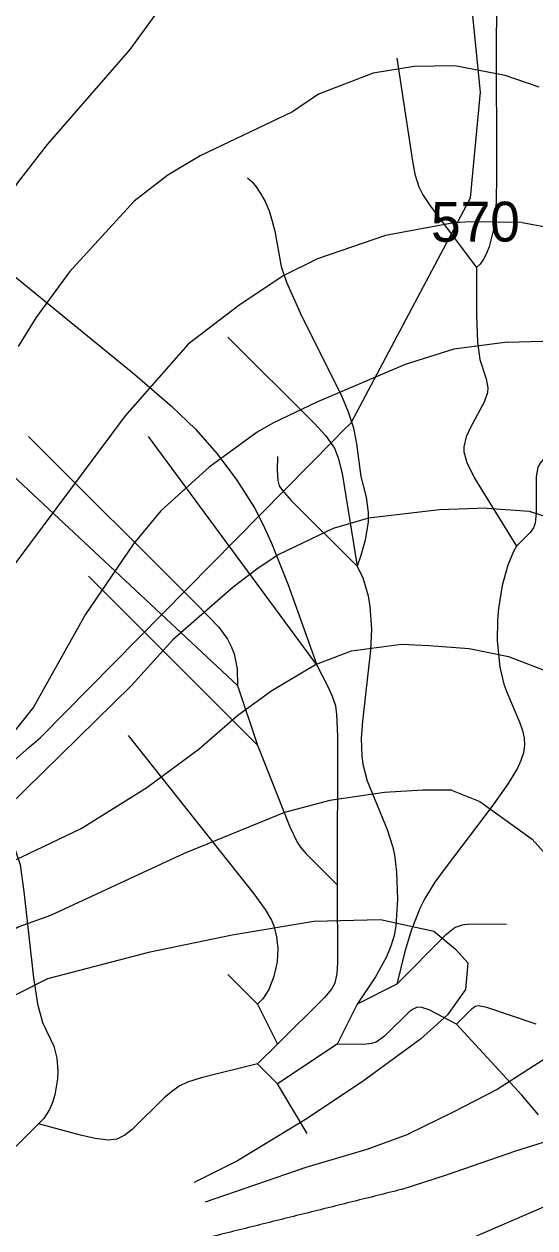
# Model space of a CAD drawing. Extents: x -709584 to -702006, y -1161789 to -1157496.
# Drawn here: x -706590.6 to -706462.3, y -1158463.2 to -1158160.9 of the extents above; entities that cross this region are included whole.
import ezdxf

# ---------------------------------------------------------------- set-up
doc = ezdxf.new("R2010")
doc.units = 0
for name, color, linetype in [('120_vrstevnice hlavní', 7, 'Continuous'), ('121_vrstevnice hlavní_popis', 7, 'Continuous'), ('122_vrstevnice základní', 7, 'Continuous'), ('408_BPEJ_linie', 7, 'Continuous'), ('411_akumulovaný odtok', 7, 'Continuous')]:
    doc.layers.add(name, color=color, linetype=linetype)

msp = doc.modelspace()

# ---------------------------------------------------------------- linework, layer by layer
at = {"layer": '120_vrstevnice hlavní'}
for points in [[(-706465.49, -1158210.75), (-706478.4, -1158210.55), (-706482.68, -1158210.83), (-706499.82, -1158213.98), (-706516.97, -1158219.83), (-706525.54, -1158224.12), (-706536.68, -1158231.55), (-706549.4, -1158241.26), (-706565.26, -1158259.27), (-706592.97, -1158296.41), (-706602.69, -1158311.7), (-706614.66, -1158334.43)], [(-706465.49, -1158210.75), (-706457.4, -1158212.2), (-706445.84, -1158215.99), (-706434.55, -1158221.69), (-706425.49, -1158219.2), (-706412.53, -1158232.56)], [(-706653.83, -1158481.13), (-706653.45, -1158468.69), (-706650.37, -1158458.2), (-706642.97, -1158447.7), (-706630.4, -1158433.27), (-706622.4, -1158425.42), (-706611.26, -1158415.99), (-706598.97, -1158407.7), (-706584.69, -1158400.56), (-706558.97, -1158393.84), (-706538.4, -1158389.56), (-706517.83, -1158386.13), (-706501.08, -1158385.71), (-706487.69, -1158388.66)], [(-706487.68, -1158388.66), (-706482.23, -1158393.17), (-706479.17, -1158396.59), (-706479.74, -1158403.27), (-706484.32, -1158409.65), (-706491.07, -1158415.78)], [(-706491.07, -1158415.78), (-706505.68, -1158426.47), (-706519.97, -1158435.98), (-706537.01, -1158446.36), (-706547.91, -1158451.77)]]:
    msp.add_lwpolyline(points, dxfattribs=at)
for points in [[(-706465.49, -1158210.75), (-706465.49, -1158210.75)], [(-706487.69, -1158388.66), (-706487.68, -1158388.66)], [(-706491.07, -1158415.78), (-706491.07, -1158415.78)]]:
    msp.add_open_spline(points, degree=1, dxfattribs=at)
at = {"layer": '122_vrstevnice základní'}
for points in [[(-706552.83, -1158151.83), (-706564.11, -1158167.26), (-706584.83, -1158191.12), (-706592.11, -1158200.55), (-706599.97, -1158212.41), (-706602.97, -1158220.98), (-706624.26, -1158271.27), (-706627.26, -1158279.84), (-706638.55, -1158305.55), (-706651.4, -1158329.27), (-706658.69, -1158339.84), (-706668.83, -1158351.7), (-706682.98, -1158366.41), (-706692.41, -1158377.41), (-706703.83, -1158388.7), (-706708.12, -1158392.13), (-706719.26, -1158399.42), (-706726.12, -1158402.7), (-706735.26, -1158405.99), (-706746.69, -1158408.7), (-706776.41, -1158413.42), (-706815.27, -1158417.84)], [(-706461.25, -1158176.73), (-706469.82, -1158173.83), (-706482.4, -1158171.4), (-706492.68, -1158171.55), (-706502.97, -1158173.26), (-706516.68, -1158178.55), (-706523.25, -1158182.98), (-706546.4, -1158193.98), (-706554.54, -1158198.83), (-706562.97, -1158205.41), (-706579.26, -1158223.12), (-706587.69, -1158234.69), (-706592.11, -1158241.83)], [(-706469.24, -1158240.81), (-706482.65, -1158242.55), (-706494.93, -1158246.35), (-706517.07, -1158255.84), (-706528.11, -1158261.12), (-706532.11, -1158263.41), (-706544.11, -1158272.12), (-706556.26, -1158283.12), (-706563.11, -1158291.41), (-706575.26, -1158309.27), (-706588.26, -1158332.41), (-706595.83, -1158341.84), (-706612.97, -1158355.98), (-706639.26, -1158375.84), (-706649.83, -1158385.27), (-706657.69, -1158393.56)], [(-706469.24, -1158240.81), (-706460.4, -1158240.52), (-706453.02, -1158242.71), (-706447.99, -1158245.29), (-706441.27, -1158250.72), (-706410.95, -1158280.04), (-706409.09, -1158280.04), (-706402.66, -1158277.46)], [(-706474.44, -1158282.48), (-706486.25, -1158282.84), (-706504.11, -1158284.98), (-706512.97, -1158287.55), (-706526.68, -1158294.12), (-706531.83, -1158297.55), (-706538.11, -1158302.27), (-706553.26, -1158315.55), (-706563.68, -1158326.98), (-706594.83, -1158357.55), (-706609.12, -1158368.98), (-706630.12, -1158383.84), (-706647.83, -1158399.56), (-706659.26, -1158412.42), (-706670.4, -1158426.99), (-706674.94, -1158439.37)], [(-706474.44, -1158282.48), (-706463.78, -1158283.21), (-706453.71, -1158286.47)], [(-706670.07, -1158442.06), (-706660.69, -1158428.27), (-706640.55, -1158405.13), (-706618.12, -1158386.99), (-706598.97, -1158373.7), (-706576.26, -1158362.84), (-706559.83, -1158352.55), (-706546.68, -1158342.84), (-706536.97, -1158334.41), (-706528.4, -1158328.27), (-706517.4, -1158321.7), (-706508.4, -1158318.27), (-706495.81, -1158316.6), (-706488.9, -1158316.93), (-706478.84, -1158317.72)], [(-706478.84, -1158317.72), (-706468.97, -1158319.7), (-706457.01, -1158324.28), (-706449.83, -1158329.47), (-706437.41, -1158339.1), (-706429.26, -1158344.82), (-706403.71, -1158361.71), (-706400.98, -1158365.5), (-706401.01, -1158367.37), (-706401.25, -1158372.12), (-706401.89, -1158381.39), (-706402.9, -1158393.27), (-706403.74, -1158401.54), (-706405.96, -1158409.64), (-706409.39, -1158417.05), (-706413.85, -1158423.43), (-706418.49, -1158428.43), (-706424, -1158431.72), (-706430.71, -1158434.14), (-706437.07, -1158436.05), (-706450.38, -1158438.66), (-706467.24, -1158443.87), (-706484.62, -1158449.93), (-706495.77, -1158453.5)], [(-706483.27, -1158353.28), (-706490.46, -1158353.23), (-706500.11, -1158353.84), (-706513.83, -1158355.84), (-706525.25, -1158358.84), (-706550.4, -1158369.13), (-706583.97, -1158384.7), (-706591.97, -1158387.56), (-706614.12, -1158400.41), (-706629.12, -1158411.99), (-706643.83, -1158425.56), (-706650.4, -1158432.7), (-706657.64, -1158442.72), (-706661.83, -1158450.54), (-706661.83, -1158461.15)], [(-706483.27, -1158353.28), (-706476.13, -1158356.08), (-706462.99, -1158365.58), (-706453.14, -1158376.57), (-706447.28, -1158385.73), (-706444.87, -1158391.85), (-706444.69, -1158396.68), (-706445.88, -1158402.36), (-706448.8, -1158408.05), (-706453.09, -1158414.61), (-706459.45, -1158420.48), (-706471.84, -1158428.44), (-706483.03, -1158434.15), (-706494.03, -1158439.56)], [(-706545.07, -1158456.62), (-706519.81, -1158447.95), (-706504.49, -1158443.43), (-706494.16, -1158439.62)], [(-706454.57, -1158455.55), (-706498.38, -1158474.44)]]:
    msp.add_lwpolyline(points, dxfattribs=at)
for points in [[(-706469.24, -1158240.81), (-706469.24, -1158240.81)], [(-706474.44, -1158282.48), (-706474.44, -1158282.48)], [(-706478.84, -1158317.72), (-706478.84, -1158317.72)], [(-706483.27, -1158353.28), (-706483.27, -1158353.28)], [(-706494.03, -1158439.56), (-706494.16, -1158439.62)], [(-706495.88, -1158453.53), (-706544.07, -1158465.52)], [(-706495.77, -1158453.5), (-706495.88, -1158453.53)]]:
    msp.add_open_spline(points, degree=1, dxfattribs=at)
at = {"layer": '408_BPEJ_linie'}
msp.add_lwpolyline([(-706726, -1158488.5), (-706694, -1158443.5), (-706687.01, -1158436.02), (-706685.49, -1158434.4), (-706668.46, -1158416.19), (-706662.77, -1158410.1), (-706658.54, -1158405.59), (-706643.74, -1158389.75), (-706643.5, -1158389.5), (-706603.24, -1158354.54), (-706598.99, -1158350.84), (-706596.83, -1158348.97), (-706589.4, -1158342.52), (-706586.5, -1158340), (-706512.81, -1158265.37), (-706510.54, -1158263.06), (-706508.5, -1158261), (-706480.2, -1158207.71), (-706478.5, -1158204.5), (-706476, -1158178), (-706478, -1158158)], dxfattribs=at)
at = {"layer": '411_akumulovaný odtok'}
for p, q in [((-706611.99, -1158257), (-706536.99, -1158327)), ((-706559.49, -1158264.5), (-706516.99, -1158322)), ((-706574.49, -1158299.5), (-706531.99, -1158342)), ((-706536.99, -1158327), (-706531.99, -1158342)), ((-706539.49, -1158399.5), (-706531.99, -1158407)), ((-706496.99, -1158402), (-706506.99, -1158407)), ((-706531.99, -1158407), (-706526.99, -1158417)), ((-706506.99, -1158407), (-706511.99, -1158417)), ((-706526.99, -1158417), (-706531.99, -1158422)), ((-706511.99, -1158417), (-706526.99, -1158427)), ((-706526.99, -1158427), (-706531.99, -1158422)), ((-706519.49, -1158439.5), (-706526.99, -1158427)), ((-706586.99, -1158437), (-706601.99, -1158452))]:
    msp.add_line(p, q, dxfattribs=at)
for points in [[(-706459.49, -1158134.5), (-706464.81, -1158141.61), (-706468.69, -1158147.38), (-706470.41, -1158150.72), (-706471.41, -1158154.05), (-706471.87, -1158157.61), (-706472.08, -1158163.12), (-706471.96, -1158200.3), (-706472.1, -1158207.93), (-706472.69, -1158212.47), (-706473.81, -1158216.83), (-706474.57, -1158218.67), (-706475.36, -1158220.1), (-706476.11, -1158221.16), (-706476.99, -1158222)], [(-706496.99, -1158169.5), (-706493.1, -1158195.31), (-706492.46, -1158198.62), (-706491.5, -1158201.8), (-706490.5, -1158203.77), (-706488.66, -1158206.58), (-706476.99, -1158222)], [(-706534.49, -1158199.5), (-706533.37, -1158200.54), (-706532.35, -1158201.8), (-706531.21, -1158203.48), (-706530.08, -1158205.5), (-706529.1, -1158207.84), (-706528.31, -1158210.36), (-706527.68, -1158212.93), (-706526.03, -1158221.77), (-706524.73, -1158225.72), (-706521.26, -1158233.43), (-706510.85, -1158254.42), (-706509.21, -1158258.3), (-706507.92, -1158262.25), (-706507.13, -1158266.34), (-706506.01, -1158274.48), (-706504.72, -1158279.68), (-706504.17, -1158283.54), (-706504.22, -1158285.87), (-706504.96, -1158290.48), (-706506.03, -1158294.34), (-706506.99, -1158297)], [(-706598.1, -1158220.23), (-706562.83, -1158248.87), (-706553.49, -1158256.93), (-706547.61, -1158262.62), (-706542.17, -1158268.83), (-706537.21, -1158275.42), (-706532.79, -1158282.37), (-706530.66, -1158286.48), (-706528.49, -1158291.25), (-706524.28, -1158301.71), (-706516.99, -1158322)], [(-706476.99, -1158222), (-706476.99, -1158234.03), (-706476.74, -1158240.77), (-706476.14, -1158245.17), (-706474.55, -1158249.99), (-706474.13, -1158252.21), (-706474.26, -1158253.41), (-706475.09, -1158255.83), (-706478.46, -1158262.02), (-706479.62, -1158264.52), (-706480.21, -1158267.04), (-706480.15, -1158268.34), (-706479.44, -1158270.95), (-706477.53, -1158274.89), (-706466.99, -1158292)], [(-706539.49, -1158239.5), (-706517.57, -1158261.26), (-706514.9, -1158264.19), (-706512.7, -1158267.37), (-706511.71, -1158269.82), (-706510.73, -1158273.76), (-706506.99, -1158297)], [(-706589.49, -1158264.5), (-706547.43, -1158306.48), (-706541.73, -1158312.37), (-706539.57, -1158315.37), (-706538.63, -1158317.15), (-706537.89, -1158319.03), (-706537.1, -1158322.82), (-706536.99, -1158327)], [(-706454.49, -1158264.5), (-706459.87, -1158269.76), (-706461, -1158271.17), (-706461.55, -1158272.18), (-706461.99, -1158274.61), (-706461.98, -1158283.75), (-706462.24, -1158286.25), (-706462.67, -1158287.37), (-706463.51, -1158288.54), (-706466.99, -1158292)], [(-706526.99, -1158269.5), (-706527.06, -1158272.88), (-706526.89, -1158275.48), (-706526.52, -1158276.81), (-706525.84, -1158277.95), (-706523.53, -1158280.52), (-706506.99, -1158297)], [(-706466.99, -1158292), (-706467.69, -1158293.3), (-706469.11, -1158296.8), (-706470.53, -1158301.85), (-706471.46, -1158307.66), (-706471.71, -1158310.56), (-706471.79, -1158315.73), (-706471.12, -1158322.37), (-706470.13, -1158326.62), (-706469.41, -1158328.65), (-706466.09, -1158336.39), (-706465.45, -1158338.26), (-706465.03, -1158340.13), (-706464.92, -1158341.97), (-706465.21, -1158343.91), (-706465.84, -1158345.83), (-706466.72, -1158347.75), (-706469, -1158351.56), (-706473.06, -1158357.26), (-706484.65, -1158372.49), (-706487.42, -1158376.36), (-706490, -1158380.48), (-706491.25, -1158383), (-706493.38, -1158388.52), (-706495.06, -1158394.12), (-706496.99, -1158402)], [(-706506.99, -1158297), (-706505.58, -1158299.97), (-706504.24, -1158304.43), (-706503.77, -1158307.12), (-706503.38, -1158312.81), (-706503.58, -1158318.11), (-706505.66, -1158335.9), (-706505.93, -1158340.3), (-706505.82, -1158344.63), (-706505.54, -1158346.76), (-706504.43, -1158350.91), (-706499.44, -1158363.13), (-706498.1, -1158367.3), (-706497.63, -1158369.46), (-706497.08, -1158373.88), (-706496.85, -1158380.61), (-706497.22, -1158387.32), (-706497.7, -1158389.78), (-706498.5, -1158392.41), (-706499.61, -1158395.07), (-706502.35, -1158400.13), (-706506.99, -1158407)], [(-706516.99, -1158322), (-706514.42, -1158327.02), (-706513.24, -1158329.69), (-706512.45, -1158332.11), (-706512.13, -1158334.23), (-706511.94, -1158339.68), (-706511.99, -1158377)], [(-706564.49, -1158339.5), (-706532.94, -1158379.27), (-706530.1, -1158383.2), (-706528.51, -1158385.92), (-706527.9, -1158387.35), (-706527.19, -1158390.1), (-706526.89, -1158392.97), (-706527.08, -1158396.36), (-706527.86, -1158400.02), (-706529.16, -1158403.33), (-706530.66, -1158405.63), (-706531.99, -1158407)], [(-706531.99, -1158342), (-706523.84, -1158362.48), (-706522.14, -1158366.15), (-706521.29, -1158367.47), (-706519.79, -1158369.25), (-706511.99, -1158377)], [(-706599.49, -1158359.5), (-706597.95, -1158360.97), (-706595.92, -1158363.28), (-706593.85, -1158366.33), (-706592.91, -1158368.21), (-706591.65, -1158372), (-706590.66, -1158378.66), (-706588.29, -1158400.36), (-706587.29, -1158406.91), (-706585.99, -1158411.55), (-706583.2, -1158417.54), (-706582.43, -1158420.55), (-706582.14, -1158423.82), (-706582.23, -1158425.74), (-706582.94, -1158429.77), (-706583.53, -1158431.69), (-706584.28, -1158433.41), (-706585.7, -1158435.67), (-706586.99, -1158437)], [(-706511.99, -1158377), (-706511.89, -1158396.69), (-706512.04, -1158399.3), (-706512.61, -1158401.75), (-706513.45, -1158403.24), (-706515.15, -1158405.31), (-706526.99, -1158417)], [(-706469.49, -1158387), (-706478.73, -1158386.92), (-706480.63, -1158387.11), (-706482.35, -1158387.73), (-706484.83, -1158389.75), (-706496.99, -1158402)], [(-706461.99, -1158412), (-706474.43, -1158407.81), (-706476.5, -1158407.4), (-706477.24, -1158407.55), (-706478.25, -1158408.2), (-706481.99, -1158412)], [(-706481.99, -1158412), (-706488.89, -1158408.41), (-706490.71, -1158407.8), (-706491.86, -1158407.77), (-706492.89, -1158408.2), (-706493.88, -1158408.93), (-706500.09, -1158415.06), (-706502.18, -1158416.52), (-706503.37, -1158416.88), (-706505.3, -1158417.09), (-706511.99, -1158417)], [(-706461.4, -1158434.73), (-706465.57, -1158429.84), (-706481.99, -1158412)], [(-706531.99, -1158422), (-706546.16, -1158425.45), (-706549.55, -1158426.58), (-706551.67, -1158427.6), (-706553.64, -1158429), (-706555.5, -1158430.62), (-706563.48, -1158438.45), (-706565.33, -1158439.89), (-706567.31, -1158440.87), (-706569.42, -1158441.15), (-706572.81, -1158440.75), (-706576.49, -1158439.89), (-706586.99, -1158437)]]:
    msp.add_lwpolyline(points, dxfattribs=at)

# ---------------------------------------------------------------- texts
at = {"layer": '121_vrstevnice hlavní_popis'}
msp.add_text('570', height=10, rotation=0.1724, dxfattribs=at).set_placement((-706488.4, -1158215.57))

doc.saveas('drawing.dxf')
